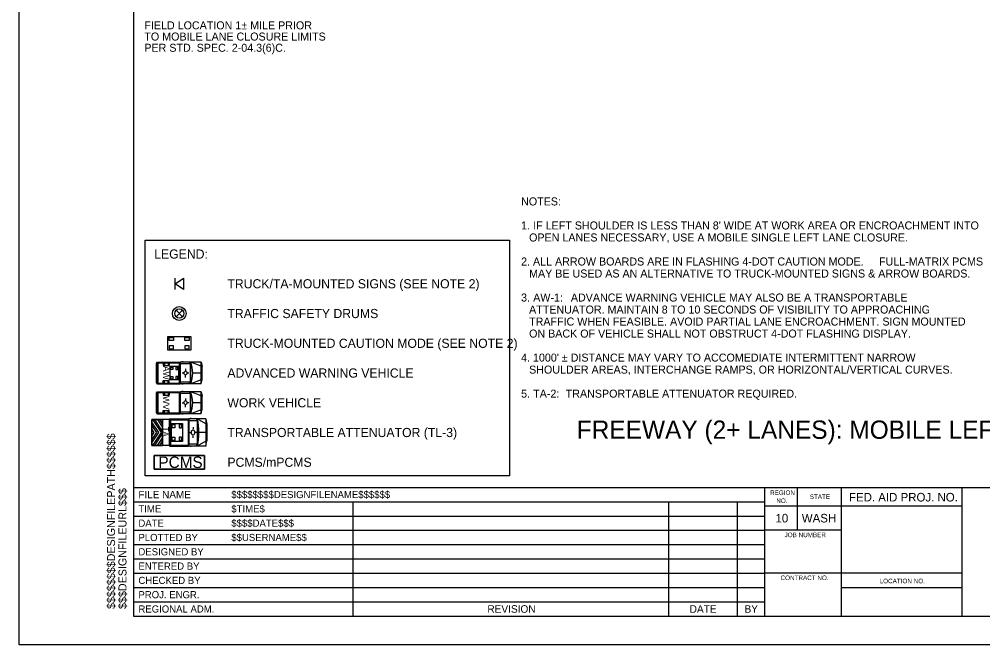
# Model space of a CAD drawing. Extents: x 0 to 17, y 0 to 11.
# Drawn here: x 0 to 8.43, y 0 to 5.47 of the extents above; entities that cross this region are included whole.
import ezdxf

# ---------------------------------------------------------------- set-up
doc = ezdxf.new("R2010")
doc.units = 0
for name, color, linetype in [('SH_GI_PlotLimits', 7, 'Continuous'), ('SH_GI_SheetBorder1', 7, 'Continuous'), ('SH_GI_SheetBorder2', 7, 'Continuous'), ('SH_GI_SheetBorder3', 7, 'Continuous'), ('SH_GI_SheetTextInCells', 7, 'Continuous'), ('SH_GI_TitleBlockText', 7, 'Continuous'), ('TR_WZ_PCMS', 7, 'Continuous'), ('TR_WZ_PortableChangeMessageSign', 7, 'Continuous'), ('TR_WZ_PortableSignMountBlk-Org', 7, 'Continuous'), ('TR_WZ_ProtectiveVehicle', 7, 'Continuous'), ('TR_WZ_TrafficSafetyDrum', 7, 'Continuous'), ('TR_WZ_TransportableAttenuator', 7, 'Continuous'), ('TR_WZ_WorkZoneTextCurrent', 7, 'Continuous')]:
    doc.layers.add(name, color=color, linetype=linetype)

msp = doc.modelspace()

# ---------------------------------------------------------------- linework, layer by layer
at = {"layer": 'SH_GI_PlotLimits'}
msp.add_lwpolyline([(0, 11), (17, 11), (17, 0), (0, 0)], close=True, dxfattribs=at)
at = {"layer": 'SH_GI_SheetBorder1'}
for p, q in [((8.245, 1.2125), (6.52, 1.2125)), ((1, 1.125), (2.92, 1.125)), ((2.92, 1.125), (6.52, 1.125)), ((1, 1), (2.92, 1)), ((2.92, 1), (6.52, 1)), ((1, 0.875), (2.92, 0.875)), ((2.92, 0.875), (6.52, 0.875)), ((1, 0.75), (2.92, 0.75)), ((2.92, 0.75), (6.52, 0.75)), ((1, 0.625), (2.92, 0.625)), ((2.92, 0.625), (6.52, 0.625)), ((1, 0.5), (2.92, 0.5)), ((2.92, 0.5), (6.52, 0.5)), ((7.1913, 0.5), (8.245, 0.5)), ((1, 0.375), (2.92, 0.375))]:
    msp.add_line(p, q, dxfattribs=at)
at = {"layer": 'SH_GI_SheetBorder2'}
for p, q in [((6.8073, 1), (6.8073, 1.375)), ((7.1913, 1), (6.52, 1)), ((8.245, 0.625), (6.52, 0.625)), ((2.92, 0.375), (6.52, 0.375))]:
    msp.add_line(p, q, dxfattribs=at)
at = {"layer": 'SH_GI_SheetBorder3'}
for p, q in [((1, 10.75), (1, 0.25)), ((1, 1.375), (16.75, 1.375)), ((6.52, 0.25), (6.52, 1.375)), ((7.1913, 0.25), (7.1913, 1.375)), ((8.245, 0.25), (8.245, 1.375)), ((1, 1.25), (6.52, 1.25)), ((2.92, 0.25), (2.92, 1.25)), ((5.68, 0.25), (5.68, 1.25)), ((6.28, 0.25), (6.28, 1.25)), ((1, 0.25), (16.75, 0.25))]:
    msp.add_line(p, q, dxfattribs=at)
at = {"layer": 'TR_WZ_PCMS'}
for points in [[(1.6191, 1.655), (1.6191, 1.535), (1.1791, 1.535), (1.1791, 1.655), (1.6191, 1.655)], [(1.1791, 1.655), (1.1791, 1.535), (1.6191, 1.535), (1.6191, 1.655), (1.1791, 1.655)]]:
    msp.add_lwpolyline(points, dxfattribs=at)
at = {"layer": 'TR_WZ_PortableSignMountBlk-Org'}
msp.add_line((1.3631, 3.105), (1.3631, 3.205), dxfattribs=at)
msp.add_lwpolyline([(1.3631, 3.155), (1.435, 3.205), (1.435, 3.105)], close=True, dxfattribs=at)
at = {"layer": 'TR_WZ_ProtectiveVehicle'}
for p, q in [((1.1993, 2.288), (1.1993, 2.462)), ((1.2035, 2.4678), (1.2078, 2.4678)), ((1.2078, 2.2822), (1.2078, 2.4678)), ((1.2085, 2.471), (1.406, 2.471)), ((1.2085, 2.279), (1.2085, 2.471)), ((1.2141, 2.2867), (1.2141, 2.4633)), ((1.2141, 2.4633), (1.4004, 2.4633)), ((1.2586, 2.4633), (1.2586, 2.4413)), ((1.2692, 2.4633), (1.2692, 2.4413)), ((1.3018, 2.4633), (1.3018, 2.4413)), ((1.3114, 2.4633), (1.3114, 2.4413)), ((1.4004, 2.2867), (1.4004, 2.4633)), ((1.406, 2.279), (1.406, 2.471)), ((1.4086, 2.279), (1.4086, 2.471)), ((1.59, 2.471), (1.4086, 2.471)), ((1.4976, 2.4561), (1.4086, 2.4561)), ((1.4334, 2.4737), (1.4225, 2.4737)), ((1.4881, 2.4561), (1.4976, 2.471)), ((1.4976, 2.279), (1.4976, 2.471)), ((1.4993, 2.279), (1.4993, 2.471)), ((1.59, 2.4358), (1.4993, 2.471)), ((1.59, 2.279), (1.59, 2.471)), ((1.59, 2.471), (1.5989, 2.4322)), ((1.1993, 2.3885), (1.2078, 2.3849)), ((1.1993, 2.3615), (1.2078, 2.3651)), ((1.2016, 2.375), (1.2055, 2.375)), ((1.2035, 2.3723), (1.2035, 2.3777)), ((1.2586, 2.4413), (1.3114, 2.4413)), ((1.4245, 2.3757), (1.4388, 2.3754)), ((1.4406, 2.3753), (1.4406, 2.3753)), ((1.4535, 2.4119), (1.4537, 2.3975)), ((1.4831, 2.3749), (1.471, 2.3749)), ((1.59, 2.375), (1.5171, 2.375)), ((1.5989, 2.3178), (1.5989, 2.4322)), ((1.2035, 2.2822), (1.2078, 2.2822)), ((1.2085, 2.279), (1.406, 2.279)), ((1.2141, 2.2867), (1.4004, 2.2867)), ((1.2586, 2.3087), (1.3114, 2.3087)), ((1.2586, 2.2867), (1.2586, 2.3087)), ((1.2692, 2.2867), (1.2692, 2.3087)), ((1.3018, 2.2867), (1.3018, 2.3087)), ((1.3114, 2.2867), (1.3114, 2.3087)), ((1.4976, 2.2939), (1.4086, 2.2939)), ((1.59, 2.279), (1.4086, 2.279)), ((1.4334, 2.2763), (1.4225, 2.2763)), ((1.4541, 2.3369), (1.4541, 2.3525)), ((1.4976, 2.279), (1.4861, 2.2939)), ((1.59, 2.3142), (1.4993, 2.279)), ((1.59, 2.279), (1.5989, 2.3178)), ((1.1993, 2.028), (1.1993, 2.202)), ((1.2035, 2.2078), (1.2078, 2.2078)), ((1.2078, 2.0222), (1.2078, 2.2078)), ((1.2085, 2.211), (1.406, 2.211)), ((1.2085, 2.019), (1.2085, 2.211)), ((1.2141, 2.0267), (1.2141, 2.2033)), ((1.2141, 2.2033), (1.4004, 2.2033)), ((1.2586, 2.2033), (1.2586, 2.1813)), ((1.2692, 2.2033), (1.2692, 2.1813)), ((1.3018, 2.2033), (1.3018, 2.1813)), ((1.3114, 2.2033), (1.3114, 2.1813)), ((1.4004, 2.0267), (1.4004, 2.2033)), ((1.406, 2.019), (1.406, 2.211)), ((1.4086, 2.019), (1.4086, 2.211)), ((1.59, 2.211), (1.4086, 2.211)), ((1.4976, 2.1961), (1.4086, 2.1961)), ((1.4334, 2.2137), (1.4225, 2.2137)), ((1.4881, 2.1961), (1.4976, 2.211)), ((1.4976, 2.019), (1.4976, 2.211)), ((1.4993, 2.019), (1.4993, 2.211)), ((1.59, 2.1758), (1.4993, 2.211)), ((1.59, 2.019), (1.59, 2.211)), ((1.59, 2.211), (1.5989, 2.1722)), ((1.1993, 2.1285), (1.2078, 2.1249)), ((1.2016, 2.115), (1.2055, 2.115)), ((1.2035, 2.1123), (1.2035, 2.1177)), ((1.2586, 2.1813), (1.3114, 2.1813)), ((1.4245, 2.1157), (1.4388, 2.1154)), ((1.4406, 2.1153), (1.4406, 2.1153)), ((1.4535, 2.1519), (1.4537, 2.1375)), ((1.4831, 2.1149), (1.471, 2.1149)), ((1.59, 2.115), (1.5171, 2.115)), ((1.5989, 2.0578), (1.5989, 2.1722)), ((1.1993, 2.1015), (1.2078, 2.1051)), ((1.2141, 2.0267), (1.4004, 2.0267)), ((1.2586, 2.0487), (1.3114, 2.0487)), ((1.2586, 2.0267), (1.2586, 2.0487)), ((1.2692, 2.0267), (1.2692, 2.0487)), ((1.3018, 2.0267), (1.3018, 2.0487)), ((1.3114, 2.0267), (1.3114, 2.0487)), ((1.4976, 2.0339), (1.4086, 2.0339)), ((1.4541, 2.0769), (1.4541, 2.0925)), ((1.4976, 2.019), (1.4861, 2.0339)), ((1.59, 2.0542), (1.4993, 2.019)), ((1.59, 2.019), (1.5989, 2.0578)), ((1.2035, 2.0222), (1.2078, 2.0222)), ((1.2085, 2.019), (1.406, 2.019)), ((1.59, 2.019), (1.4086, 2.019)), ((1.4334, 2.0163), (1.4225, 2.0163))]:
    msp.add_line(p, q, dxfattribs=at)
for centre, major_axis, start_param, end_param in [((1.2035, 2.462), (0, 0.00586), 0, 1.570796), ((1.3697, 2.375), (0, 0.2015), 4.215667, 5.208926), ((1.2035, 2.288), (0, -0.00586), 4.712389, 6.283185), ((1.2035, 2.202), (0, 0.00586), 0, 1.570796), ((1.3697, 2.115), (0, 0.2015), 4.215667, 5.208926), ((1.2035, 2.028), (0, -0.00586), 4.712389, 6.283185)]:
    msp.add_ellipse(centre, major_axis=major_axis, ratio=0.73155, start_param=start_param, end_param=end_param, dxfattribs=at)
for centre, major_axis in [((1.2035, 2.375), (0, -0.0027)), ((1.4541, 2.375), (0, -0.0185)), ((1.2035, 2.115), (0, -0.0027)), ((1.4541, 2.115), (0, -0.0185))]:
    msp.add_ellipse(centre, major_axis=major_axis, ratio=0.73155, dxfattribs=at)
at = {"layer": 'TR_WZ_TrafficSafetyDrum'}
for p, q in [((1.3708, 2.9233), (1.4273, 2.8667)), ((1.4273, 2.9233), (1.3708, 2.8667))]:
    msp.add_line(p, q, dxfattribs=at)
for radius in [0.06, 0.06, 0.04]:
    msp.add_circle((1.3991, 2.895), radius, dxfattribs=at)
at = {"layer": 'TR_WZ_TransportableAttenuator'}
for p, q in [((1.159, 1.9172), (1.159, 1.9464)), ((1.2191, 1.8559), (1.159, 1.9464)), ((1.159, 1.9464), (1.159, 1.9172)), ((1.1652, 1.9679), (1.1856, 1.9679)), ((1.1652, 1.9679), (1.2401, 1.8552)), ((1.1856, 1.9679), (1.1652, 1.9679)), ((1.2534, 1.8651), (1.1856, 1.9679)), ((1.2078, 1.9679), (1.2281, 1.9679)), ((1.2281, 1.9679), (1.2078, 1.9679)), ((1.2078, 1.9679), (1.2534, 1.8983)), ((1.2534, 1.9297), (1.2281, 1.9679)), ((1.2534, 1.7426), (1.2534, 1.9679)), ((1.3178, 1.9679), (1.2534, 1.9679)), ((1.3101, 1.9637), (1.3101, 1.7462)), ((1.3137, 1.971), (1.3172, 1.971)), ((1.3172, 1.971), (1.3172, 1.7389)), ((1.3178, 1.9749), (1.4803, 1.9749)), ((1.3178, 1.9749), (1.3178, 1.7349)), ((1.3178, 1.9675), (1.3178, 1.7426)), ((1.3224, 1.9654), (1.3224, 1.7445)), ((1.3224, 1.9654), (1.4757, 1.9654)), ((1.4757, 1.9654), (1.4757, 1.7445)), ((1.4803, 1.9749), (1.4803, 1.7349)), ((1.4825, 1.9749), (1.4825, 1.7349)), ((1.6317, 1.9749), (1.4825, 1.9749)), ((1.5557, 1.9563), (1.4825, 1.9563)), ((1.5028, 1.9783), (1.4938, 1.9783)), ((1.5557, 1.9749), (1.5462, 1.9563)), ((1.5557, 1.9749), (1.5557, 1.7349)), ((1.5571, 1.9749), (1.5571, 1.7349)), ((1.6317, 1.931), (1.5571, 1.9749)), ((1.6317, 1.9749), (1.6317, 1.7349)), ((1.6317, 1.9749), (1.639, 1.9265)), ((1.159, 1.9172), (1.1998, 1.8562)), ((1.159, 1.8239), (1.159, 1.8863)), ((1.1799, 1.8553), (1.159, 1.8863)), ((1.159, 1.8863), (1.159, 1.8239)), ((1.1998, 1.8562), (1.159, 1.7947)), ((1.159, 1.7653), (1.2191, 1.8559)), ((1.159, 1.8239), (1.1799, 1.8553)), ((1.2401, 1.8552), (1.1652, 1.7424)), ((1.2534, 1.9297), (1.2534, 1.8983)), ((1.2534, 1.8983), (1.2534, 1.9297)), ((1.2534, 1.8651), (1.2534, 1.845)), ((1.2534, 1.845), (1.2534, 1.8651)), ((1.3101, 1.8718), (1.3172, 1.8674)), ((1.312, 1.855), (1.3153, 1.855)), ((1.3137, 1.8583), (1.3137, 1.8516)), ((1.4881, 1.8551), (1.5014, 1.8551)), ((1.5051, 1.8545), (1.5051, 1.8545)), ((1.5199, 1.9025), (1.5199, 1.8831)), ((1.5517, 1.8551), (1.5384, 1.8551)), ((1.6317, 1.855), (1.5717, 1.855)), ((1.639, 1.9265), (1.639, 1.7834)), ((1.159, 1.7653), (1.159, 1.7947)), ((1.159, 1.7947), (1.159, 1.7653)), ((1.1852, 1.7424), (1.2534, 1.845)), ((1.2534, 1.8119), (1.2072, 1.7424)), ((1.2288, 1.7424), (1.2534, 1.7787)), ((1.2534, 1.8119), (1.2534, 1.7787)), ((1.2534, 1.7787), (1.2534, 1.8119)), ((1.3101, 1.838), (1.3172, 1.8426)), ((1.5199, 1.8074), (1.5199, 1.8268)), ((1.6317, 1.7789), (1.5571, 1.7349)), ((1.6317, 1.7349), (1.639, 1.7834)), ((1.1852, 1.7424), (1.1652, 1.7424)), ((1.1652, 1.7424), (1.1852, 1.7424)), ((1.2288, 1.7424), (1.2072, 1.7424)), ((1.2072, 1.7424), (1.2288, 1.7424)), ((1.3178, 1.7426), (1.2534, 1.7426)), ((1.3137, 1.7389), (1.3172, 1.7389)), ((1.3178, 1.7349), (1.4803, 1.7349)), ((1.3224, 1.7445), (1.4757, 1.7445)), ((1.5557, 1.7535), (1.4825, 1.7535)), ((1.6317, 1.7349), (1.4825, 1.7349)), ((1.5028, 1.7316), (1.4938, 1.7316)), ((1.5479, 1.7535), (1.5557, 1.7349))]:
    msp.add_line(p, q, dxfattribs=at)
for points in [[(1.4991, 2.695), (1.4991, 2.575), (1.2991, 2.575), (1.2991, 2.695)], [(1.3491, 2.685), (1.3491, 2.6583), (1.3116, 2.6583), (1.3116, 2.685)], [(1.4866, 2.685), (1.4866, 2.6583), (1.4491, 2.6583), (1.4491, 2.685)], [(1.3491, 2.585), (1.3491, 2.6117), (1.3116, 2.6117), (1.3116, 2.585)], [(1.4866, 2.585), (1.4866, 2.6117), (1.4491, 2.6117), (1.4491, 2.585)], [(1.3204, 2.435), (1.3924, 2.435), (1.3924, 2.315), (1.3204, 2.315)], [(1.3264, 2.4275), (1.3424, 2.4275), (1.3424, 2.405), (1.3264, 2.405)], [(1.3864, 2.4275), (1.3704, 2.4275), (1.3704, 2.405), (1.3864, 2.405)], [(1.3264, 2.345), (1.3424, 2.345), (1.3424, 2.3225), (1.3264, 2.3225)], [(1.3864, 2.345), (1.3704, 2.345), (1.3704, 2.3225), (1.3864, 2.3225)], [(1.2534, 1.7424), (1.159, 1.7424), (1.159, 1.9679), (1.2534, 1.9679)], [(1.3304, 1.935), (1.4264, 1.935), (1.4264, 1.775), (1.3304, 1.775)], [(1.3384, 1.925), (1.3597, 1.925), (1.3597, 1.895), (1.3384, 1.895)], [(1.4184, 1.925), (1.397, 1.925), (1.397, 1.895), (1.4184, 1.895)], [(1.3384, 1.815), (1.3597, 1.815), (1.3597, 1.785), (1.3384, 1.785)], [(1.4184, 1.815), (1.397, 1.815), (1.397, 1.785), (1.4184, 1.785)]]:
    msp.add_lwpolyline(points, close=True, dxfattribs=at)
msp.add_lwpolyline([(1.2534, 1.9679), (1.159, 1.9679), (1.159, 1.7424), (1.2534, 1.7426)], dxfattribs=at)
for centre, major_axis, start_param, end_param in [((1.3137, 1.9637), (0, 0.00732), 6.283185, 7.853982), ((1.4504, 1.8549), (0, 0.2519), 4.215852, 5.209111), ((1.3137, 1.7462), (0, -0.00732), 4.712389, 6.283185)]:
    msp.add_ellipse(centre, major_axis=major_axis, ratio=0.481608, start_param=start_param, end_param=end_param, dxfattribs=at)
for centre, major_axis, ratio in [((1.3137, 1.8549), (0, -0.00338), 0.481608), ((1.5199, 1.8549), (0, -0.0231), 0.642144), ((1.5199, 1.8549), (0, 0.0231), 0.642144)]:
    msp.add_ellipse(centre, major_axis=major_axis, ratio=ratio, dxfattribs=at)
at = {"layer": 'TR_WZ_WorkZoneTextCurrent'}
msp.add_lwpolyline([(1.1, 3.535), (4.2886, 3.535), (4.2886, 1.475), (1.1, 1.475)], close=True, dxfattribs=at)

# ---------------------------------------------------------------- texts
at = {"layer": 'SH_GI_SheetTextInCells'}
for s, height, p in [('REGION', 0.04, (6.5662, 1.3088)), ('FILE NAME', 0.065, (1.042, 1.28)), ('NO.', 0.04, (6.6206, 1.2387)), ('STATE', 0.04, (6.9129, 1.2738)), ('FED. AID PROJ. NO.', 0.075, (7.2558, 1.252)), ('TIME', 0.0625, (1.042, 1.1562)), ('10', 0.075, (6.6136, 1.0688)), ('WASH', 0.075, (6.8434, 1.0688)), ('DATE', 0.0625, (1.042, 1.0312)), ('PLOTTED BY', 0.0625, (1.042, 0.9062)), ('JOB NUMBER', 0.04, (6.6925, 0.94)), ('DESIGNED BY', 0.0625, (1.042, 0.7812)), ('ENTERED BY', 0.0625, (1.042, 0.6562)), ('CHECKED BY', 0.0625, (1.042, 0.5312)), ('CONTRACT NO.', 0.04, (6.6574, 0.565)), ('LOCATION NO.', 0.04, (7.5244, 0.537)), ('PROJ. ENGR.', 0.0625, (1.042, 0.4062)), ('REGIONAL ADM.', 0.0625, (1.042, 0.2812)), ('REVISION', 0.066, (4.0938, 0.2795)), ('DATE', 0.066, (5.8627, 0.2795)), ('BY', 0.066, (6.3424, 0.2795))]:
    msp.add_text(s, height=height, dxfattribs=at).set_placement(p)
at = {"layer": 'SH_GI_TitleBlockText'}
for s, p in [('$$$$$$$$DESIGNFILEPATH$$$$$$', (0.8377, 0.3125)), ('$$$DESIGNFILEURL$$$', (0.9375, 0.3125))]:
    msp.add_text(s, height=0.07, rotation=90, dxfattribs=at).set_placement(p)
for s, p in [('$$$$$$$$DESIGNFILENAME$$$$$$', (1.8545, 1.2812)), ('$TIME$', (1.8545, 1.1562)), ('$$$$DATE$$$', (1.8545, 1.0312)), ('$$USERNAME$$', (1.8545, 0.9062))]:
    msp.add_text(s, height=0.0625, dxfattribs=at).set_placement(p)
at = {"layer": 'TR_WZ_PCMS'}
msp.add_text('PCMS', height=0.1, rotation=360, dxfattribs=at).set_placement((1.2173, 1.545))
at = {"layer": 'TR_WZ_PortableChangeMessageSign'}
for s, p in [('FIELD LOCATION 1± MILE PRIOR ', (1.0938, 5.3789)), ('TO MOBILE LANE CLOSURE LIMITS ', (1.0938, 5.2809)), ('PER STD. SPEC. 2-04.3(6)C.', (1.0938, 5.1829))]:
    msp.add_text(s, height=0.07, rotation=360, dxfattribs=at).set_placement(p)
at = {"layer": 'TR_WZ_ProtectiveVehicle'}
for s, p in [('AW', (1.257, 2.4371)), ('WV', (1.257, 2.1743))]:
    msp.add_text(s, height=0.056, rotation=270, dxfattribs=at).set_placement(p)
at = {"layer": 'TR_WZ_TransportableAttenuator'}
msp.add_text('TA', height=0.048, rotation=270, dxfattribs=at).set_placement((1.2571, 1.9045))
at = {"layer": 'TR_WZ_WorkZoneTextCurrent'}
for s, height, p in [('NOTES:', 0.07, (4.3886, 3.8397)), ('1. ', 0.07, (4.3886, 3.6297)), ("IF LEFT SHOULDER IS LESS THAN 8' WIDE AT WORK AREA OR ENCROACHMENT INTO ", 0.07, (4.4943, 3.6297)), ('OPEN LANES NECESSARY, USE A MOBILE SINGLE LEFT LANE CLOSURE.', 0.07, (4.4586, 3.5247)), ('LEGEND:', 0.08, (1.18, 3.375)), ('2. ALL ARROW BOARDS ARE IN FLASHING 4-DOT CAUTION MODE. ', 0.07, (4.3886, 3.3147)), ('FULL-MATRIX PCMS ', 0.07, (7.5188, 3.3147)), ('MAY BE USED AS AN ALTERNATIVE TO TRUCK-MOUNTED SIGNS & ARROW BOARDS.', 0.07, (4.4586, 3.2097)), ('TRUCK/TA-MOUNTED SIGNS (SEE NOTE 2)', 0.08, (1.82, 3.115)), ('3. ', 0.07, (4.3886, 2.9997)), ('AW-1:', 0.07, (4.4943, 2.9997)), (' ADVANCE WARNING VEHICLE MAY ALSO BE A TRANSPORTABLE ', 0.07, (4.7978, 2.9997)), ('ATTENUATOR. MAINTAIN 8 TO 10 SECONDS OF VISIBILITY TO APPROACHING ', 0.07, (4.4586, 2.8947)), ('TRAFFIC SAFETY DRUMS', 0.08, (1.82, 2.855)), ('TRAFFIC WHEN FEASIBLE. AVOID PARTIAL LANE ENCROACHMENT. SIGN MOUNTED ', 0.07, (4.4586, 2.7897)), ('ON BACK OF VEHICLE SHALL NOT OBSTRUCT 4-DOT FLASHING DISPLAY.', 0.07, (4.4586, 2.6847)), ('TRUCK-MOUNTED CAUTION MODE (SEE NOTE 2)', 0.08, (1.82, 2.595)), ("4. 1000' ± DISTANCE MAY VARY TO ACCOMEDIATE INTERMITTENT NARROW ", 0.07, (4.3886, 2.4747)), ('ADVANCED WARNING VEHICLE', 0.08, (1.82, 2.335)), ('SHOULDER AREAS, INTERCHANGE RAMPS, OR HORIZONTAL/VERTICAL CURVES. ', 0.07, (4.4586, 2.3697)), ('5. ', 0.07, (4.3886, 2.1597)), ('TA-2:', 0.07, (4.4943, 2.1597)), (' TRANSPORTABLE ATTENUATOR REQUIRED.', 0.07, (4.7527, 2.1597)), ('WORK VEHICLE', 0.08, (1.82, 2.075)), ('FREEWAY (2+ LANES): MOBILE LEFT SHOULDER CLOSURE, EXCLUDING PAVEMENT MARKING OPERATIONS', 0.16, (4.8752, 1.7997)), ('TRANSPORTABLE ATTENUATOR (TL-3)', 0.08, (1.82, 1.815)), ('PCMS/mPCMS', 0.08, (1.82, 1.555))]:
    msp.add_text(s, height=height, rotation=360, dxfattribs=at).set_placement(p)

doc.saveas('drawing.dxf')
